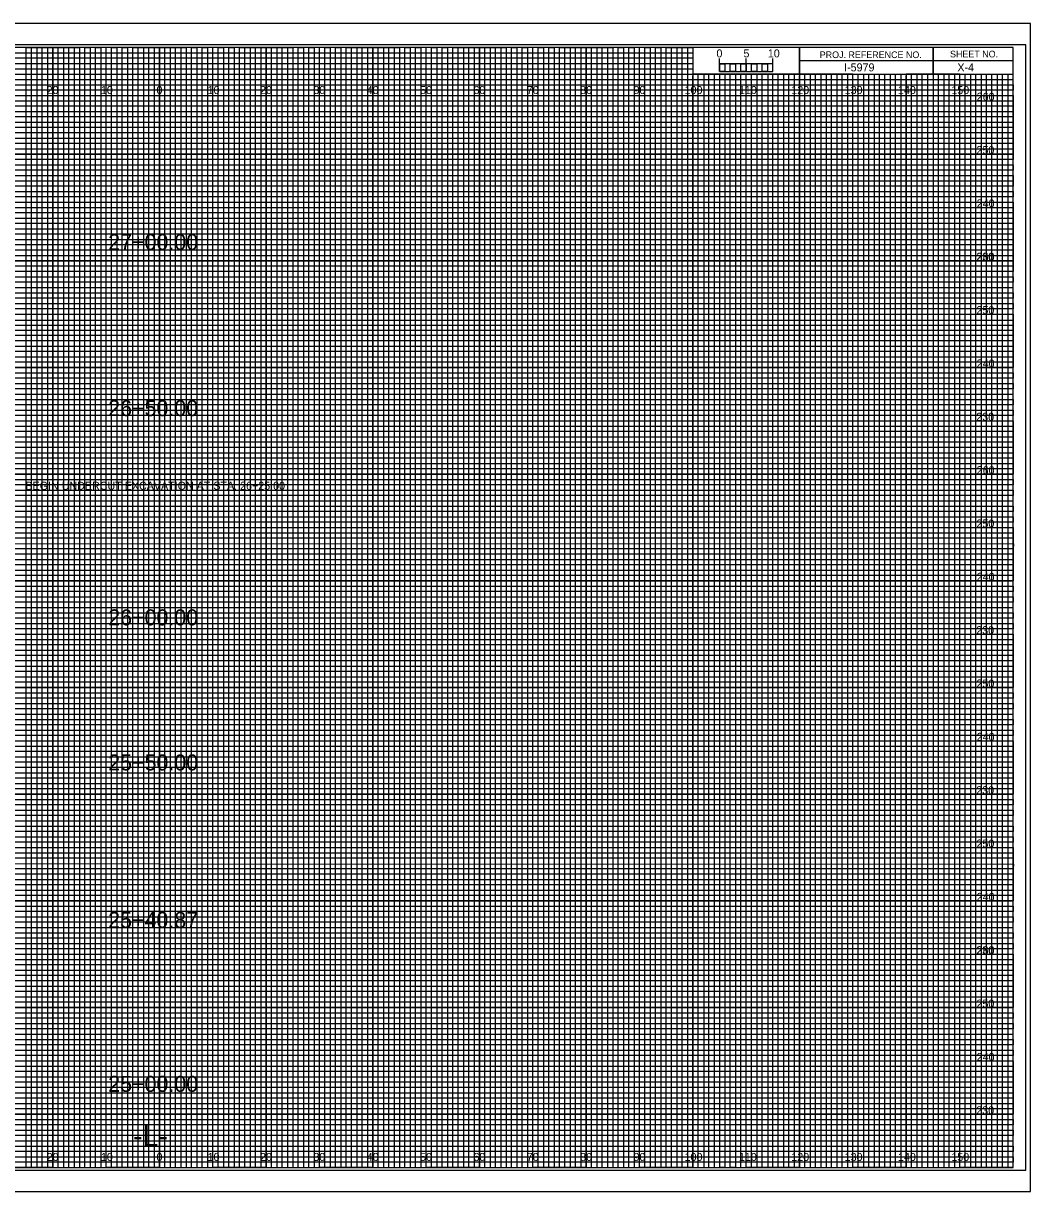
# Model space of a CAD drawing. Extents: x -13 to 359, y -5 to 2854.
# Drawn here: x 134.5 to 323.3, y 655.5 to 874.5 of the extents above; entities that cross this region are included whole.
import ezdxf

# ---------------------------------------------------------------- set-up
doc = ezdxf.new("R2010")
doc.units = 0
for name, color, linetype in [('Exist CMT Pavement', 7, 'Continuous'), ('Exist Cross Section Cell', 7, 'Continuous'), ('Exist XS Ground Line', 7, 'Continuous'), ('Prop CMT Conc Surface', 7, 'Continuous'), ('Prop CMT Concrete Structures', 7, 'Continuous'), ('Prop CMT DNC', 7, 'Continuous'), ('Prop CMT Pvmt Course 1', 7, 'Continuous'), ('Prop CMT Pvmt Course 1 CG', 7, 'Continuous'), ('Prop CMT Pvmt Course 1 Wedge', 7, 'Continuous'), ('Prop CMT Pvmt Course 2', 7, 'Continuous'), ('Prop CMT Pvmt Course 2 Wedge', 7, 'Continuous'), ('Prop CMT Pvmt Course 3', 7, 'Continuous'), ('Prop CMT Pvmt Course 3 Wedge', 7, 'Continuous'), ('Prop CMT Pvmt Wedge Surface 2', 7, 'Continuous'), ('Prop CMT Shear Line', 7, 'Continuous'), ('Prop CMT Slope Grass', 7, 'Continuous'), ('Prop CMT Subgrade Earthwork', 7, 'Continuous'), ('Scratch_Level_0', 7, 'Continuous')]:
    doc.layers.add(name, color=color, linetype=linetype)

msp = doc.modelspace()

# ---------------------------------------------------------------- linework, layer by layer
at = {"layer": 'Exist XS Ground Line'}
for p, q in [((150, 870), (140, 870)), ((140, 870), (140, 660)), ((150, 660), (150, 870)), ((170, 870), (160, 870)), ((160, 870), (160, 660)), ((170, 660), (170, 870)), ((190, 870), (180, 870)), ((180, 870), (180, 660)), ((190, 660), (190, 870)), ((210, 870), (200, 870)), ((200, 870), (200, 660)), ((210, 660), (210, 870)), ((230, 870), (220, 870)), ((220, 870), (220, 660)), ((230, 660), (230, 870)), ((250, 870), (240, 870)), ((240, 870), (240, 660)), ((250, 660), (250, 870)), ((260, 870), (260, 660)), ((270, 660), (270, 865)), ((290, 865), (280, 865)), ((280, 865), (280, 660)), ((290, 660), (290, 865)), ((310, 865), (300, 865)), ((300, 865), (300, 660)), ((310, 660), (310, 865)), ((140, 660), (130, 660)), ((160, 660), (150, 660)), ((180, 660), (170, 660)), ((200, 660), (190, 660)), ((220, 660), (210, 660)), ((240, 660), (230, 660)), ((260, 660), (250, 660)), ((280, 660), (270, 660)), ((300, 660), (290, 660)), ((320, 660), (310, 660)), ((320, 660), (320, 660))]:
    msp.add_line(p, q, dxfattribs=at)
for points in [[(0, 860), (320, 860), (320, 850), (0, 850)], [(0, 840), (320, 840), (320, 830), (0, 830)], [(0, 820), (320, 820), (320, 810), (0, 810)], [(0, 800), (320, 800), (320, 790), (0, 790)], [(0, 780), (320, 780), (320, 770), (0, 770)], [(0, 760), (320, 760), (320, 750), (0, 750)], [(0, 740), (320, 740), (320, 730), (0, 730)], [(0, 720), (320, 720), (320, 710), (0, 710)], [(0, 700), (320, 700), (320, 690), (0, 690)], [(0, 680), (320, 680), (320, 670), (0, 670)]]:
    msp.add_lwpolyline(points, dxfattribs=at)
at = {"layer": 'Prop CMT Conc Surface'}
for p, q in [((265, 865.49), (265, 867.9)), ((265, 866.9), (265, 867.9)), ((270, 865.49), (270, 867.9)), ((275, 865.49), (275, 867.9)), ((275, 866.9), (275, 867.9))]:
    msp.add_line(p, q, dxfattribs=at)
for points in [[(275, 866.9), (265, 866.9), (265, 865.49), (275, 865.49)], [(265, 866.9), (266, 866.9), (266, 865.49), (265, 865.49)], [(267, 866.9), (268, 866.9), (268, 865.49), (267, 865.49)], [(269, 866.9), (270, 866.9), (270, 865.49), (269, 865.49)], [(271, 866.9), (272, 866.9), (272, 865.49), (271, 865.49)], [(273, 866.9), (274, 866.9), (274, 865.49), (273, 865.49)]]:
    msp.add_lwpolyline(points, close=True, dxfattribs=at)
at = {"layer": 'Prop CMT Concrete Structures'}
for p, q in [((305, 870), (305, 865)), ((305, 865), (305, 870)), ((280, 867.5), (280, 865)), ((320, 867.49), (280, 867.49)), ((280, 865), (320, 865))]:
    msp.add_line(p, q, dxfattribs=at)
for points in [[(320, 870), (0, 870), (0, 660), (320, 660)], [(280, 870), (260, 870), (260, 865.03), (280, 865.03)], [(320, 870), (280, 870), (280, 865), (320, 865)]]:
    msp.add_lwpolyline(points, close=True, dxfattribs=at)
at = {"layer": 'Prop CMT DNC'}
for p, q in [((323.3, 874.5), (-13.4, 874.5)), ((-13.4, 655.5), (323.3, 655.5))]:
    msp.add_line(p, q, dxfattribs=at)
at = {"layer": 'Prop CMT Pvmt Course 1'}
for p, q in [((0, 869), (260, 869)), ((260, 867.98), (0, 867.98)), ((260, 869), (260, 867.98)), ((0, 867), (260, 867)), ((260, 865.89), (0, 865.89)), ((260, 867), (260, 865.89)), ((0, 864), (320, 864))]:
    msp.add_line(p, q, dxfattribs=at)
for points in [[(0, 863), (270, 863), (320, 863), (320, 862), (0, 862)], [(0, 861), (320, 861), (320, 859), (0, 859)], [(0, 858), (320, 858), (320, 857), (0, 856.98)], [(0, 856), (320, 856), (320, 854), (0, 854)], [(0, 853), (320, 853), (320, 852), (0, 852)], [(0, 851), (320, 851), (320, 849), (0, 849)], [(0, 848), (320, 848), (320, 847), (0, 847)], [(0, 846), (320, 846), (320, 844), (0, 844)], [(0, 843), (320, 843), (320, 842), (0, 842)], [(0, 841), (320, 841), (320, 839), (0, 839)], [(0, 838), (320, 838), (320, 837), (0, 837)], [(0, 836), (320, 836), (320, 833.95), (320, 833), (320, 832), (0, 832)], [(0, 834), (320, 834), (320, 833), (0, 833)], [(0, 831), (320, 831), (320, 829), (0, 829.03)], [(0, 829.03), (320, 829), (320, 828), (0, 828)], [(0, 827), (320, 827), (320, 826), (0, 826)], [(0, 824), (320, 824), (320, 823), (0, 823)], [(0, 822), (320, 822), (320, 821), (0, 821)], [(-0.07, 818.89), (320, 818.89), (320, 817.88), (-0.07, 817.88)], [(0, 817), (320, 817), (320, 816), (0, 816)], [(0, 814), (320, 814), (320, 813), (0, 813)], [(0, 812), (320, 812), (320, 811), (0, 811)], [(0, 809), (320, 809), (320, 808), (0, 808)], [(0, 807), (320, 807), (320, 806), (0, 806)], [(0, 804), (320, 804), (320, 803), (0, 803)], [(0, 802), (320, 802), (320, 801), (0, 801)], [(0, 799), (320, 799), (319.99, 797.98), (0, 798)], [(0, 797), (320, 797), (320, 796), (0, 796)], [(0, 794), (320, 794), (320, 793), (0, 793)], [(0, 792), (320, 792), (320, 791), (0, 791)], [(0, 789), (320, 789), (320, 788), (0, 788)], [(0, 787), (320, 787), (320, 786), (0, 786)], [(0, 784), (320, 784), (320, 783), (0, 783)], [(0, 782), (320, 782), (320, 781), (0, 781)], [(0, 779), (320, 779), (320, 778), (0, 778)], [(0, 776.99), (320.07, 776.91), (320, 776), (0, 776)], [(0, 774), (320, 774), (320, 773), (0, 773)], [(0, 772), (320, 772), (320, 771), (0, 771)], [(0, 769), (320, 769), (320, 768), (0, 768)], [(0, 767), (320, 767), (320, 766), (0, 766)], [(0, 764), (320, 764), (320, 763), (0, 763)], [(0, 762), (320, 762), (320, 761), (0, 761)], [(0, 759), (320, 759), (320, 758), (0, 758)], [(0, 757), (320, 757), (320, 756), (0, 756)], [(0, 754), (320, 754), (320, 753), (0, 753)], [(0, 752), (320, 752), (320, 751), (0, 751)], [(0, 749), (320, 749), (320, 748), (0, 748)], [(0, 747), (320, 747), (320, 746), (0, 746)], [(0, 744), (320, 744), (320, 743), (0, 743)], [(0, 742), (320, 742), (320, 741), (0, 741)], [(0, 739), (320, 739), (319.99, 737.98), (0, 738)], [(0, 737), (320, 737), (320, 736), (0, 736)], [(0, 734), (320, 734), (320, 733), (0, 733)], [(0, 732), (320, 732), (320, 731), (0, 731)], [(0, 729), (320, 729), (320, 728), (0, 728)], [(0, 727), (320, 727), (320, 726), (0, 726)], [(0, 724), (320, 724), (320, 723), (0, 723)], [(0, 722), (320, 722), (320, 721), (0, 721)], [(0, 719), (320, 719), (320, 718), (0, 718)], [(0, 716.99), (320.07, 716.91), (320, 716), (0, 716)], [(0, 714), (320, 714), (320, 713), (0, 713)], [(0, 712), (320, 712), (320, 711), (0, 711)], [(0, 709), (320, 709), (320, 708), (0, 708)], [(0, 707), (320, 707), (320, 706), (0, 706)], [(0, 704), (320, 704), (320, 703), (0, 703)], [(0, 702), (320, 702), (320, 701), (0, 701)], [(0, 699), (320, 699), (320, 698), (0, 698)], [(0, 697), (320, 697), (320, 696), (0, 696)], [(0, 694), (320, 694), (320, 693), (0, 693)], [(0, 692), (320, 692), (320, 691), (0, 691)], [(0, 689), (320, 689), (320, 688), (0, 688)], [(0, 687), (320, 687), (320, 686), (0, 686)], [(0, 684), (320, 684), (320, 683), (0, 683)], [(0, 682), (320, 682), (320, 681), (0, 681)], [(0, 679), (320, 679), (320, 678), (0, 678)], [(0, 677), (320, 677), (320, 676), (0, 676)], [(0, 674), (320, 674), (320, 673), (0, 673)], [(0, 672), (320, 672), (320, 671), (0, 671)], [(0, 669), (320, 669), (320, 668), (0, 668)], [(0, 667), (320, 667), (320, 666), (0, 666)], [(0, 664), (320, 664), (320, 663), (0, 663)], [(0, 662), (320, 662), (320, 661), (0, 661)]]:
    msp.add_lwpolyline(points, dxfattribs=at)
at = {"layer": 'Prop CMT Pvmt Course 1 CG'}
for p, q in [((267, 865), (266.01, 865)), ((266.01, 865), (266.01, 660)), ((267, 660), (267, 865)), ((269, 865), (268, 865)), ((268, 865), (268, 660)), ((269, 660), (269, 865)), ((266.01, 660), (265, 660)), ((268, 660), (267, 660))]:
    msp.add_line(p, q, dxfattribs=at)
for points in [[(135, 660), (136, 660), (136, 870), (137, 870), (137, 660)], [(137, 660), (138, 660), (138, 870), (139, 870), (139, 660)], [(140, 660), (141, 660), (141, 870), (142, 870), (142, 660)], [(142, 660), (143, 660), (143, 870), (144, 870), (144, 660)], [(145, 660), (146, 660), (146, 870), (147, 870), (147, 660)], [(147, 660), (148, 660), (148, 870), (149, 870), (149, 660)], [(150, 660), (151, 660), (151, 870), (152, 870), (152, 660)], [(152, 660), (153, 660), (153, 870), (154, 870), (154, 660)], [(155, 660), (156, 660), (156, 870), (157, 870), (157, 660)], [(157, 660), (158, 660), (158, 870), (159, 870), (159, 660)], [(160, 660), (161, 660), (161, 870), (162, 870), (162, 660)], [(162, 660), (163, 660), (163, 870), (164, 870), (164, 660)], [(165, 660), (166, 660), (166, 870), (167, 870), (167, 660)], [(167, 660), (168, 660), (168, 870), (169, 870), (169, 660)], [(170, 660), (171, 660), (171, 870), (172, 870), (172, 660)], [(172, 660), (173, 660), (173, 870), (174, 870), (174, 660)], [(175, 660), (176, 660), (176, 870), (177, 870), (177, 660)], [(177, 660), (178, 660), (178, 870), (179, 870), (179, 660)], [(180, 660), (181, 660), (181, 870), (182, 870), (182, 660)], [(182, 660), (183, 660), (183, 870), (184, 870), (184, 660)], [(185, 660), (186, 660), (186, 870), (187, 870), (187, 660)], [(187, 660), (188, 660), (188, 870), (189, 870), (189, 660)], [(190, 660), (191, 660), (191, 870), (192, 870), (192, 660)], [(192, 660), (193, 660), (193, 870), (194, 870), (194, 660)], [(195, 660), (196, 660), (196, 870), (197, 870), (197, 660)], [(197, 660), (198, 660), (198, 870), (199, 870), (199, 660)], [(200, 660), (201, 660), (201, 870), (202, 870), (202, 660)], [(202, 660), (203, 660), (203, 870), (204, 870), (204, 660)], [(205, 660), (206, 660), (206, 870), (207, 870), (207, 660)], [(207, 660), (208, 660), (208, 870), (209, 870), (209, 660)], [(210, 660), (211, 660), (211, 870), (212, 870), (212, 660)], [(212, 660), (213, 660), (213, 870), (214, 870), (214, 660)], [(215, 660), (216, 660), (216, 870), (217, 870), (217, 660)], [(217, 660), (218, 660), (218, 870), (219, 870), (219, 660)], [(220, 660), (221, 660), (221, 870), (222, 870), (222, 660)], [(222, 660), (223, 660), (223, 870), (224, 870), (224, 660)], [(225, 660), (226, 660), (226, 870), (227, 870), (227, 660)], [(227, 660), (228, 660), (228, 870), (229, 870), (229, 660)], [(230, 660), (231, 660), (231, 870), (232, 870), (232, 660)], [(232, 660), (233, 660), (233, 870), (234, 870), (234, 660)], [(235, 660), (236, 660), (236, 870), (237, 870), (237, 660)], [(237, 660), (238, 660), (238, 870), (239, 870), (239, 660)], [(240, 660), (241, 660), (241, 870), (242, 870), (242, 660)], [(242, 660), (243, 660), (243, 870), (244, 870), (244, 660)], [(245, 660), (246, 660), (246, 870), (247, 870), (247, 660)], [(247, 660), (248, 660), (248, 870), (249, 870), (249, 660)], [(250, 660), (251, 660), (251, 870), (252, 870), (252, 660)], [(252, 660), (253, 660), (253, 870), (254, 870), (254, 660)], [(255, 660), (256, 660), (256, 870), (257, 870), (257, 660)], [(257, 660), (258, 660), (258, 870), (259, 870), (259, 660)], [(260, 660), (261, 660), (261, 865), (262.02, 865), (262.02, 660)], [(262, 660), (263, 660), (263, 865), (263.99, 865), (263.99, 660)], [(270, 660), (270.98, 660), (270.98, 865), (272, 865), (272, 660)], [(272, 660), (273, 660), (273, 865), (274.05, 865), (274.05, 660)], [(275, 660), (276, 660), (276, 865), (277, 865), (277, 660)], [(277, 660), (278, 660), (278, 865), (279, 865), (279, 660)], [(280, 660), (281, 660), (281, 865), (282, 865), (282, 660)], [(282, 660), (283, 660), (283, 865), (284, 865), (284, 660)], [(285, 660), (286, 660), (286, 865), (287, 865), (287, 660)], [(287, 660), (288, 660), (288, 865), (289, 865), (289, 660)], [(290, 660), (291, 660), (291, 865), (292, 865), (292, 660)], [(292, 660), (293, 660), (293, 865), (294, 865), (294, 660)], [(295, 660), (296, 660), (296, 865), (297, 865), (297, 660)], [(297, 660), (298, 660), (298, 865), (299, 865), (299, 660)], [(300, 660), (301, 660), (301, 865), (302, 865), (302, 660)], [(302, 660), (303, 660), (303, 865), (304, 865), (304, 660)], [(305, 660), (306, 660), (306, 865), (307, 865), (307, 660)], [(307, 660), (308, 660), (308, 865), (309, 865), (309, 660)], [(310, 660), (311, 660), (311, 865), (312, 865), (312, 660)], [(312, 660), (313, 660), (313, 865), (314, 865), (314, 660)], [(315, 660), (316, 660), (316, 865), (317, 865), (317, 660)], [(317, 660), (318, 660), (318, 865), (319, 865), (319, 660)]]:
    msp.add_lwpolyline(points, dxfattribs=at)
at = {"layer": 'Prop CMT Shear Line'}
for p, q in [((140, 660), (140, 870)), ((150, 660), (150, 870)), ((160, 660), (160, 870)), ((170, 660), (170, 870)), ((180, 660), (180, 870)), ((190, 660), (190, 870)), ((200, 660), (200, 870)), ((210, 660), (210, 870)), ((220, 660), (220, 870)), ((230, 660), (230, 870)), ((240, 660), (240, 870)), ((250, 660), (250, 870)), ((260, 660), (260, 864.69)), ((270, 660), (270, 864.69)), ((280, 660), (280, 864.69)), ((290, 660), (290, 864.69)), ((300, 660), (300, 864.69)), ((310, 660), (310, 864.69)), ((0, 860), (320, 860)), ((0, 850), (320, 850)), ((0, 840), (320, 840)), ((0, 830), (320, 830)), ((0, 820), (320, 820)), ((0, 810), (320, 810)), ((0, 800), (320, 800)), ((0, 790), (320, 790)), ((0, 780), (320, 780)), ((0, 770), (320, 770)), ((0, 760), (320, 760)), ((0, 750), (320, 750)), ((0, 740), (320, 740)), ((0, 730), (320, 730)), ((0, 720), (320, 720)), ((0, 710), (320, 710)), ((0, 700), (320, 700)), ((0, 690), (320, 690)), ((0, 680), (320, 680)), ((0, 670), (320, 670))]:
    msp.add_line(p, q, dxfattribs=at)
at = {"layer": 'Prop CMT Slope Grass'}
msp.add_lwpolyline([(-10.8, 659.5), (322.4, 659.5), (322.4, 870.5), (-10.8, 870.5)], close=True, dxfattribs=at)
at = {"layer": 'Prop CMT Subgrade Earthwork'}
msp.add_lwpolyline([(-13.4, 655.5), (323.3, 655.5), (323.3, 874.5), (-13.4, 874.5)], close=True, dxfattribs=at)
at = {"layer": 'Scratch_Level_0'}
for points in [[(125, 660), (135, 660), (135, 870), (145, 870), (145, 660), (155, 660), (155, 870), (165, 870), (165, 660), (175, 660), (175, 870), (185, 870), (185, 660), (195, 660), (195, 870), (205, 870), (205, 660), (215, 660), (215, 870), (225, 870), (225, 660), (235, 660), (235, 870), (245, 870), (245, 660), (255, 660), (255, 870), (259.93, 870), (260, 870), (260, 865), (264.99, 865), (264.99, 660), (275, 660), (275, 865), (285, 865), (285, 660), (295, 660), (295, 865), (305, 865), (305, 660), (315, 660), (315, 865)], [(0, 865), (275, 865)], [(0, 845), (320, 845), (320, 855), (0, 855)], [(0, 825), (320, 825), (320, 835), (0, 835)], [(0, 805), (320, 805), (320, 815), (0, 815)], [(0, 785), (320, 785), (320, 795), (0, 795)], [(0, 765), (320, 765), (320, 775), (0, 775)], [(0, 745), (320, 745), (320, 755), (0, 755)], [(0, 725), (320, 725), (320, 735), (0, 735)], [(0, 705), (320, 705), (320, 715), (0, 715)], [(0, 685), (320, 685), (320, 695), (0, 695)], [(0, 665), (320, 665), (320, 675), (0, 675)]]:
    msp.add_lwpolyline(points, dxfattribs=at)

# ---------------------------------------------------------------- texts
at = {"layer": 'Exist CMT Pavement'}
for s, p in [('5', (269.47, 868.12)), ('10', (274.04, 868.12))]:
    msp.add_text(s, height=1.5, dxfattribs=at).set_placement(p)
at = {"layer": 'Exist Cross Section Cell'}
for s, p in [('20', (138.86, 861.25)), ('10', (149.04, 861.25)), ('0', (159.45, 861.25)), ('0', (159.45, 861.25)), ('10', (169.04, 861.25)), ('20', (178.86, 861.25)), ('30', (188.86, 861.25)), ('40', (198.86, 861.25)), ('50', (208.86, 861.25)), ('60', (218.86, 861.25)), ('70', (228.86, 861.25)), ('80', (238.86, 861.25)), ('90', (248.86, 861.25)), ('100', (258.44, 861.25)), ('110', (268.62, 861.25)), ('120', (278.44, 861.25)), ('130', (288.44, 861.25)), ('140', (298.44, 861.25)), ('150', (308.44, 861.25)), ('20', (138.86, 661.25)), ('10', (149.04, 661.25)), ('0', (159.45, 661.25)), ('0', (159.45, 661.25)), ('10', (169.04, 661.25)), ('20', (178.86, 661.25)), ('30', (188.86, 661.25)), ('40', (198.86, 661.25)), ('50', (208.86, 661.25)), ('60', (218.86, 661.25)), ('70', (228.86, 661.25)), ('80', (238.86, 661.25)), ('90', (248.86, 661.25)), ('100', (258.44, 661.25)), ('110', (268.62, 661.25)), ('120', (278.44, 661.25)), ('130', (288.44, 661.25)), ('140', (298.44, 661.25)), ('150', (308.44, 661.25))]:
    msp.add_text(s, height=1.5, dxfattribs=at).set_placement(p)
at = {"layer": 'Prop CMT Conc Surface'}
msp.add_text('0', height=1.5, dxfattribs=at).set_placement((264.41, 868.12))
at = {"layer": 'Prop CMT Concrete Structures'}
for s, p in [('PROJ. REFERENCE NO.', (283.77, 867.99)), ('SHEET NO.', (308.19, 868.12))]:
    msp.add_text(s, height=1.25, dxfattribs=at).set_placement(p)
at = {"layer": 'Prop CMT Pvmt Course 1 Wedge'}
msp.add_text('X-4', height=1.5, dxfattribs=at).set_placement((309.57, 865.5))
at = {"layer": 'Prop CMT Pvmt Course 2'}
for s, p in [('260', (313.19, 860)), ('250', (313.15, 850)), ('240', (313.19, 840)), ('230', (313.11, 830)), ('260', (313.19, 830)), ('250', (313.15, 820)), ('240', (313.19, 810)), ('230', (313.11, 800)), ('260', (313.19, 790)), ('250', (313.15, 780)), ('240', (313.19, 770)), ('230', (313.11, 760)), ('250', (313.15, 750)), ('240', (313.19, 740)), ('230', (313.11, 730)), ('250', (313.15, 720)), ('240', (313.19, 710)), ('230', (313.11, 700)), ('260', (313.19, 700)), ('250', (313.15, 690)), ('240', (313.19, 680)), ('230', (313.11, 670))]:
    msp.add_text(s, height=1.5, dxfattribs=at).set_placement(p)
at = {"layer": 'Prop CMT Pvmt Course 2 Wedge'}
msp.add_text('I-5979', height=1.5, dxfattribs=at).set_placement((288.34, 865.5))
at = {"layer": 'Prop CMT Pvmt Course 3'}
for s, p in [('27+00.00', (150.41, 832.01)), ('26+50.00', (150.41, 800.87)), ('26+00.00', (150.41, 761.65)), ('25+50.00', (150.41, 734.46)), ('25+40.87', (150.4, 704.92)), ('25+00.00', (150.41, 674.2))]:
    msp.add_text(s, height=3, dxfattribs=at).set_placement(p)
at = {"layer": 'Prop CMT Pvmt Course 3 Wedge'}
msp.add_text('-L-', height=4, dxfattribs=at).set_placement((155.06, 664))
at = {"layer": 'Prop CMT Pvmt Wedge Surface 2'}
msp.add_text('BEGIN UNDERCUT EXCAVATION AT STA. 26+25.00', height=1.5, rotation=360, dxfattribs=at).set_placement((134.89, 787.07))

doc.saveas('drawing.dxf')
